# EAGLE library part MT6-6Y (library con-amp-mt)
AMP MT6 CONNECTOR
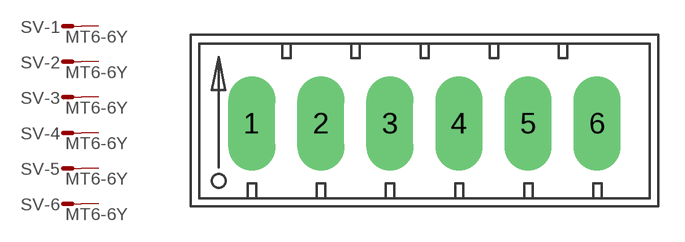
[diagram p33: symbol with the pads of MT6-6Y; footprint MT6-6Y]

Designator prefix SV; gates -1=MA -2=MA -3=MA -4=MA -5=MA -6=MA

## MT6-6Y (OC_FARNELL: unknown; OC_NEWARK: unknown)  [MT6-6Y]
1  -1:S  pas
2  -2:S  pas
3  -3:S  pas
4  -4:S  pas
5  -5:S  pas
6  -6:S  pas

## Footprint MT6-6Y (pad centres in mm)
AMP MT6 CONNECTOR
drill 1.803 long: 1 -9.906,0; 2 -5.944,0; 3 -1.981,0; 4 1.981,0; 5 5.944,0; 6 9.906,0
